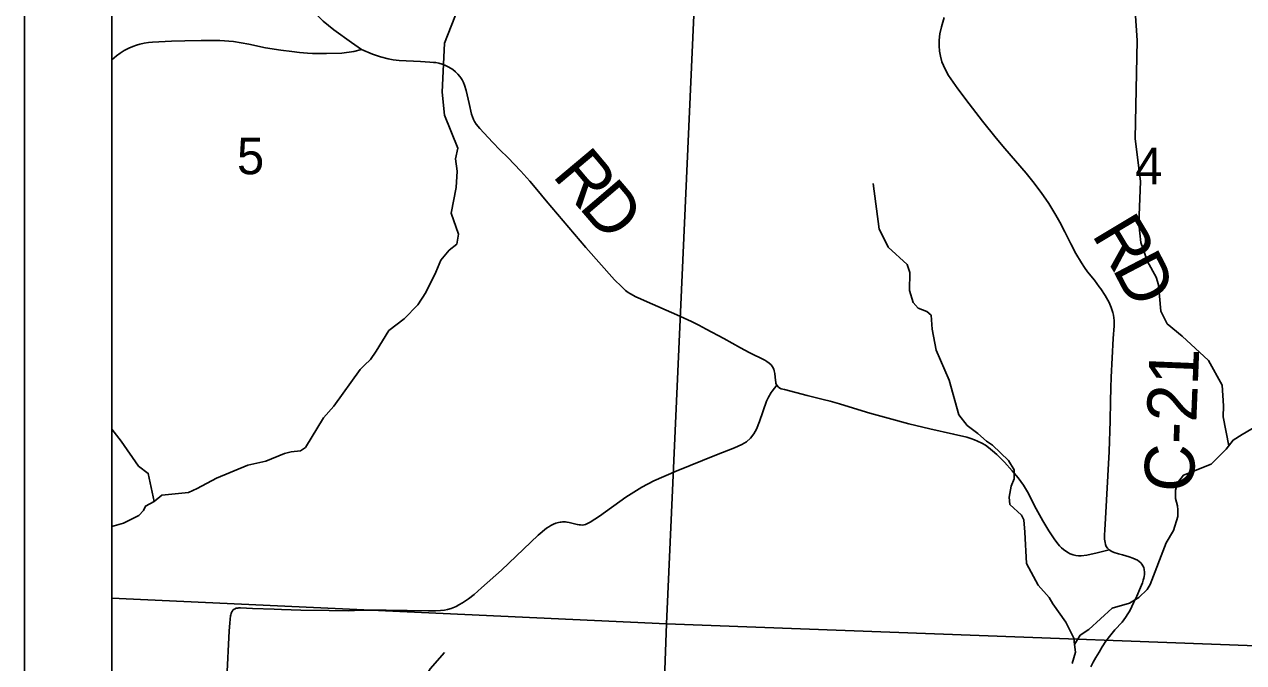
# Model space of a CAD drawing. Extents: x 0 to 34, y 0 to 22.
# Drawn here: x 23.917 to 25.311, y 17.25 to 17.98 of the extents above; entities that cross this region are included whole.
import ezdxf

# ---------------------------------------------------------------- set-up
doc = ezdxf.new("R2010")
doc.units = 0
for name, color, linetype in [('GM_X_Adjacent_County', 7, 'Continuous'), ('GM_X_County', 7, 'Continuous'), ('GM_X_County_Road', 7, 'Continuous'), ('GM_X_County_Road_Text', 7, 'Continuous'), ('GM_X_Minor_River', 7, 'Continuous'), ('GM_X_Section', 7, 'Continuous'), ('GM_X_Section_Text', 7, 'Continuous'), ('GM_X_Township', 7, 'Continuous'), ('GM_X_Township_Road', 7, 'Continuous'), ('GM_X_Township_Road_Text', 7, 'Continuous'), ('SH_Data', 7, 'Continuous')]:
    doc.layers.add(name, color=color, linetype=linetype)

msp = doc.modelspace()

# ---------------------------------------------------------------- linework, layer by layer
at = {"layer": 'GM_X_Adjacent_County'}
msp.add_lwpolyline([(28.7526, 20.9), (24.0167, 20.9), (24.0167, 14.1), (28.5181, 14.1)], dxfattribs=at)
at = {"layer": 'GM_X_County'}
msp.add_lwpolyline([(28.7526, 20.9), (24.0167, 20.9), (24.0167, 14.1), (28.5181, 14.1)], dxfattribs=at)
at = {"layer": 'GM_X_County_Road'}
for points in [[(25.157, 17.3789), (25.1552, 17.3808), (25.1537, 17.3828), (25.1529, 17.3848), (25.1524, 17.3871), (25.1518, 17.3912), (25.1518, 17.3952), (25.1521, 17.402), (25.1526, 17.4079), (25.1572, 17.4912), (25.158, 17.5266), (25.1584, 17.5486), (25.1588, 17.5641), (25.1594, 17.5764), (25.1615, 17.6207), (25.1626, 17.635), (25.1627, 17.6412), (25.1619, 17.6473), (25.1612, 17.6503), (25.1594, 17.6561), (25.157, 17.6617), (25.154, 17.667), (25.1524, 17.6697), (25.1475, 17.6774), (25.1457, 17.6799), (25.1401, 17.6872), (25.1324, 17.6969), (25.1287, 17.7019), (25.1253, 17.7071), (25.119, 17.7179), (25.1132, 17.7289), (25.1062, 17.7428), (25.1006, 17.7538), (25.0961, 17.7619), (25.0879, 17.775), (25.0792, 17.7878), (25.0699, 17.8003), (25.0621, 17.8099), (25.0376, 17.8379), (25.0277, 17.8499), (25.0123, 17.8694), (24.997, 17.889), (24.984, 17.9062), (24.9785, 17.9138), (24.9735, 17.9216), (24.9704, 17.9271), (24.9677, 17.9328), (24.9657, 17.937), (24.9641, 17.9435), (24.963, 17.9492), (24.9628, 17.9554), (24.9628, 17.9621), (24.9636, 17.9691), (24.9652, 17.977), (24.9684, 17.988)], [(25.1361, 17.2452), (25.1387, 17.2503), (25.1419, 17.2557), (25.1455, 17.262), (25.149, 17.2681), (25.1534, 17.2745), (25.1575, 17.2798), (25.1637, 17.2872), (25.1718, 17.2961), (25.1757, 17.3015), (25.1784, 17.3058), (25.1806, 17.3092), (25.183, 17.3141), (25.1852, 17.3191), (25.1885, 17.326), (25.1928, 17.3359), (25.195, 17.341), (25.1961, 17.344), (25.1968, 17.3465), (25.1972, 17.3484), (25.1974, 17.3508), (25.1974, 17.3535), (25.1971, 17.3562), (25.1965, 17.3585), (25.1957, 17.3604), (25.1945, 17.3624), (25.1931, 17.3641), (25.1914, 17.3656), (25.1896, 17.3669), (25.1869, 17.3683), (25.1842, 17.3693), (25.1798, 17.3708), (25.1722, 17.373), (25.1676, 17.3742), (25.1627, 17.3757), (25.1599, 17.3769), (25.157, 17.3789)]]:
    msp.add_lwpolyline(points, dxfattribs=at)
at = {"layer": 'GM_X_Minor_River'}
for points in [[(25.1866, 17.8493), (25.189, 17.9616), (25.1845, 18.0298), (25.1877, 18.0659), (25.1947, 18.0985), (25.1999, 18.1096), (25.2047, 18.1407)], [(24.4096, 17.8262), (24.4122, 17.8383), (24.3972, 17.8762), (24.3944, 17.9023), (24.3971, 17.9585), (24.4214, 18.0212)], [(25.1866, 17.8493), (25.193, 17.8001), (25.1911, 17.7519), (25.1931, 17.7303), (25.2008, 17.7087), (25.2108, 17.6909), (25.2135, 17.6819), (25.216, 17.6519), (25.2233, 17.6375), (25.2404, 17.6232), (25.2705, 17.5954), (25.2862, 17.5674), (25.2879, 17.5435), (25.2872, 17.531), (25.2937, 17.4979)], [(24.4096, 17.8262), (24.4116, 17.8122), (24.4102, 17.7932), (24.4047, 17.7639), (24.4132, 17.7401), (24.411, 17.7287), (24.4024, 17.7218), (24.393, 17.7104), (24.387, 17.6967), (24.3758, 17.6731), (24.3664, 17.659), (24.351, 17.643), (24.3333, 17.6296), (24.319, 17.606), (24.3123, 17.5965), (24.3055, 17.59), (24.3006, 17.585), (24.2706, 17.5431), (24.2586, 17.5297), (24.238, 17.4958), (24.2323, 17.492), (24.2217, 17.4908), (24.2142, 17.4892), (24.1926, 17.4804), (24.1722, 17.4757), (24.1363, 17.461), (24.1144, 17.4491), (24.1042, 17.4445), (24.074, 17.4416), (24.0649, 17.434), (24.0551, 17.429), (24.0529, 17.4237), (24.0476, 17.418), (24.0299, 17.4095), (24.0167, 17.4054)], [(25.1174, 17.2705), (25.1166, 17.2777), (25.1074, 17.2962), (25.0925, 17.317), (25.0886, 17.3245), (25.076, 17.3385), (25.0626, 17.3634), (25.0605, 17.3991), (25.0593, 17.4131), (25.0569, 17.4184), (25.0436, 17.4308), (25.0428, 17.4392), (25.045, 17.4517), (25.0483, 17.4601), (25.0483, 17.4703), (25.0418, 17.4809), (25.0235, 17.4986), (25.0166, 17.5031), (25.0067, 17.5118), (24.9945, 17.5212), (24.985, 17.5332), (24.9741, 17.573), (24.9591, 17.6074), (24.9548, 17.6313), (24.9535, 17.6472), (24.9486, 17.6517), (24.9387, 17.6555), (24.933, 17.6619), (24.9287, 17.6755), (24.929, 17.696), (24.9259, 17.7051), (24.9042, 17.725), (24.898, 17.7383), (24.8942, 17.7458), (24.887, 17.7978)], [(25.1803, 17.3179), (25.1909, 17.3244), (25.2003, 17.3336), (25.2041, 17.3393), (25.2223, 17.3868), (25.2305, 17.4009), (25.2354, 17.4169), (25.2357, 17.4245), (25.2353, 17.4294), (25.2329, 17.4377), (25.2329, 17.4472), (25.2351, 17.4556), (25.2419, 17.4643), (25.2736, 17.4767), (25.2909, 17.4942), (25.2988, 17.5045), (25.309, 17.511), (25.3618, 17.5417), (25.4206, 17.5796), (25.4406, 17.5976), (25.4602, 17.6087), (25.4852, 17.6104), (25.5041, 17.6165)], [(24.0167, 17.517), (24.0274, 17.5032), (24.0472, 17.4745), (24.0583, 17.4662), (24.0649, 17.434)], [(25.1149, 17.2488), (25.1186, 17.2618), (25.1174, 17.2705), (25.1238, 17.2811), (25.1339, 17.2876), (25.1603, 17.3121), (25.1803, 17.3179)], [(24.3206, 16.6956), (24.3346, 16.805), (24.3412, 16.8357), (24.3513, 16.8631), (24.3583, 16.889), (24.3574, 16.9053), (24.3527, 16.9356), (24.3468, 16.9606), (24.3397, 17.0072), (24.3377, 17.0261), (24.3379, 17.0432), (24.3401, 17.0588), (24.3512, 17.0964), (24.3589, 17.131), (24.3584, 17.1511), (24.3544, 17.1825), (24.3577, 17.2023), (24.3656, 17.2163), (24.3682, 17.2217), (24.3805, 17.2426), (24.3971, 17.2613)]]:
    msp.add_lwpolyline(points, dxfattribs=at)
at = {"layer": 'GM_X_Section'}
for p, q in [((24.0167, 18.4409), (24.0167, 17.3235)), ((24.0167, 17.3235), (24.0167, 16.3224))]:
    msp.add_line(p, q, dxfattribs=at)
for points in [[(24.0167, 17.3235), (24.6507, 17.2941), (24.7007, 18.4069), (24.0167, 18.4409)], [(24.0167, 16.3224), (24.6148, 16.293), (24.6507, 17.2941), (24.0167, 17.3235)]]:
    msp.add_lwpolyline(points, dxfattribs=at)
for points in [[(24.7007, 18.4069), (25.6829, 18.3575), (25.6316, 17.2576), (24.6507, 17.2941)], [(24.6507, 17.2941), (25.6316, 17.2576), (25.601, 16.254), (24.6148, 16.293)]]:
    msp.add_lwpolyline(points, close=True, dxfattribs=at)
at = {"layer": 'GM_X_Township'}
msp.add_lwpolyline([(24.0167, 18.4402), (24.0167, 14.1), (28.5181, 14.1)], dxfattribs=at)
at = {"layer": 'GM_X_Township_Road'}
for points in [[(24.0167, 18.1589), (24.0243, 18.1562), (24.0447, 18.1487), (24.0592, 18.1432), (24.0822, 18.134), (24.099, 18.1262), (24.1044, 18.1235), (24.1098, 18.1202), (24.1198, 18.1129), (24.1412, 18.0951), (24.177, 18.0655), (24.1935, 18.0514), (24.2068, 18.0384), (24.2091, 18.036), (24.2158, 18.0289), (24.2302, 18.0135), (24.2464, 17.9954), (24.2584, 17.9836), (24.2705, 17.9739), (24.2906, 17.9592), (24.3022, 17.9513)], [(24.0167, 17.9396), (24.0221, 17.9441), (24.0261, 17.947), (24.0308, 17.95), (24.036, 17.9528), (24.0406, 17.9548), (24.0447, 17.9562), (24.0488, 17.9574), (24.0537, 17.9585), (24.0584, 17.9592), (24.063, 17.9596), (24.0847, 17.9607), (24.1002, 17.9612), (24.1188, 17.9615), (24.1403, 17.9615), (24.1556, 17.9604), (24.1733, 17.9572), (24.1925, 17.9532), (24.2098, 17.9504), (24.2225, 17.9488), (24.2314, 17.9477), (24.2405, 17.9469), (24.2461, 17.9466), (24.262, 17.9466), (24.2798, 17.9469), (24.2934, 17.9488), (24.3022, 17.9513)], [(24.3022, 17.9513), (24.3149, 17.9459), (24.3237, 17.9427), (24.3328, 17.9405), (24.3383, 17.9395), (24.3451, 17.9387), (24.3697, 17.9376), (24.3804, 17.9369), (24.3844, 17.9365), (24.387, 17.9364), (24.3906, 17.9357), (24.3942, 17.9346), (24.3975, 17.9332), (24.4021, 17.9309), (24.4066, 17.9282), (24.4097, 17.9256), (24.4122, 17.9231), (24.4146, 17.9203), (24.4156, 17.9188), (24.4173, 17.9164), (24.4189, 17.9135), (24.42, 17.9104), (24.4219, 17.9045), (24.4252, 17.8894), (24.4279, 17.8771), (24.4289, 17.8742), (24.4302, 17.8713), (24.4314, 17.869), (24.4334, 17.8659), (24.4373, 17.861), (24.452, 17.8451), (24.4608, 17.8362), (24.4695, 17.8275), (24.4844, 17.812), (24.4947, 17.8006), (24.5026, 17.7911), (24.5132, 17.7783), (24.5587, 17.7248), (24.5915, 17.6878), (24.5993, 17.68), (24.6041, 17.6756), (24.607, 17.6733), (24.6097, 17.6716), (24.6157, 17.6682), (24.621, 17.666), (24.6288, 17.6627), (24.6627, 17.6478), (24.6796, 17.6401), (24.6878, 17.636), (24.6961, 17.6313), (24.7164, 17.6205), (24.7354, 17.61), (24.7453, 17.6048), (24.7633, 17.5959), (24.7657, 17.5944), (24.7683, 17.5926), (24.7704, 17.5905), (24.7722, 17.5881), (24.7735, 17.5854), (24.7741, 17.5835), (24.7746, 17.5806), (24.775, 17.5764), (24.7759, 17.5701), (24.776, 17.5694), (24.7764, 17.5683), (24.7771, 17.5671)], [(24.1481, 17.232), (24.151, 17.2864), (24.1515, 17.2951), (24.1519, 17.2996), (24.1525, 17.3032), (24.1527, 17.3047), (24.1532, 17.3062), (24.1536, 17.3073), (24.1538, 17.3078), (24.1541, 17.3084), (24.1545, 17.309), (24.155, 17.3097), (24.1555, 17.3101), (24.1561, 17.3106), (24.1567, 17.3111), (24.1575, 17.3115), (24.1582, 17.3117), (24.159, 17.312), (24.1598, 17.3122), (24.1607, 17.3123), (24.1617, 17.3124), (24.1639, 17.3124), (24.1708, 17.3122), (24.1776, 17.3119), (24.2024, 17.311), (24.2107, 17.3107), (24.2217, 17.3102), (24.2328, 17.31), (24.2653, 17.3094), (24.2867, 17.3092), (24.3018, 17.3098), (24.3176, 17.31), (24.3302, 17.31), (24.3786, 17.309), (24.3867, 17.309), (24.3925, 17.3093), (24.3969, 17.31), (24.4006, 17.3106), (24.4047, 17.3118), (24.4102, 17.3142), (24.4135, 17.3159), (24.4175, 17.3182), (24.4245, 17.323), (24.4308, 17.3278), (24.4393, 17.3354), (24.4622, 17.3557), (24.5041, 17.3956), (24.5136, 17.4035), (24.5164, 17.4053), (24.5188, 17.4068), (24.5216, 17.4081), (24.5245, 17.4092), (24.5275, 17.4101), (24.5292, 17.4105), (24.5305, 17.4107), (24.532, 17.411), (24.5337, 17.411), (24.5353, 17.4109), (24.537, 17.4106), (24.5397, 17.4101), (24.5455, 17.4087), (24.5471, 17.4083), (24.549, 17.4078), (24.5509, 17.4075), (24.5527, 17.4073), (24.5546, 17.4072), (24.5564, 17.4074), (24.5583, 17.408), (24.5607, 17.409), (24.5636, 17.4106), (24.5741, 17.4172), (24.6044, 17.439), (24.6227, 17.4507), (24.6365, 17.4579), (24.6621, 17.469), (24.7082, 17.4877), (24.7285, 17.4954), (24.737, 17.4992), (24.7422, 17.5025), (24.7468, 17.5067), (24.7507, 17.5115), (24.7539, 17.5169), (24.7573, 17.5255), (24.7654, 17.549), (24.7675, 17.5535), (24.7685, 17.5554), (24.7694, 17.5571), (24.7705, 17.5587), (24.7718, 17.5604), (24.7771, 17.5671)], [(24.7771, 17.5671), (24.779, 17.565), (24.7806, 17.5638), (24.782, 17.5632), (24.7859, 17.5622), (24.8119, 17.5556), (24.8301, 17.5508), (24.8379, 17.5488), (24.8487, 17.5458), (24.8597, 17.5426), (24.8834, 17.5354), (24.9043, 17.5295), (24.9281, 17.523), (24.952, 17.5172), (24.9792, 17.5113), (24.9943, 17.5078), (24.9987, 17.5063), (25.003, 17.5047), (25.0065, 17.5033), (25.0114, 17.5009), (25.0156, 17.4985), (25.0192, 17.496), (25.0236, 17.4923), (25.0286, 17.488), (25.0372, 17.4792), (25.0462, 17.4691), (25.0529, 17.4612), (25.059, 17.453), (25.0638, 17.4451), (25.0736, 17.4257), (25.0811, 17.4121), (25.088, 17.4008), (25.094, 17.3916), (25.0972, 17.3873), (25.1002, 17.3836), (25.1026, 17.381), (25.1047, 17.3792), (25.1099, 17.3757), (25.1124, 17.3744), (25.1158, 17.3733), (25.1191, 17.3724), (25.122, 17.3721), (25.1252, 17.372), (25.1314, 17.3728), (25.1435, 17.3756), (25.157, 17.3789)]]:
    msp.add_lwpolyline(points, dxfattribs=at)
at = {"layer": 'SH_Data'}
for points in [[(23.9167, 21), (30.9167, 21), (30.9167, 14), (23.9167, 14)], [(24.0167, 20.9), (30.8167, 20.9), (30.8167, 14.1), (24.0167, 14.1)]]:
    msp.add_lwpolyline(points, close=True, dxfattribs=at)

# ---------------------------------------------------------------- texts
at = {"layer": 'GM_X_County_Road_Text'}
for s, height, rotation, p in [('R', 0.0568, 300.9417, (25.1364, 17.7398)), ('D', 0.0568, 297.6452, (25.16, 17.7006)), ('C-21', 0.05682, 87.6631, (25.2534, 17.4442))]:
    msp.add_text(s, height=height, rotation=rotation, dxfattribs=at).set_placement(p)
at = {"layer": 'GM_X_Section_Text'}
for s, p in [('5', (24.1597, 17.8085)), ('4', (25.1868, 17.797))]:
    msp.add_text(s, height=0.0419, rotation=0, dxfattribs=at).set_placement(p)
at = {"layer": 'GM_X_Township_Road_Text'}
for s, rotation, p in [('R', 310.018, (24.5193, 17.8069)), ('D', 310.5015, (24.5497, 17.7707))]:
    msp.add_text(s, height=0.0568, rotation=rotation, dxfattribs=at).set_placement(p)

doc.saveas('drawing.dxf')
